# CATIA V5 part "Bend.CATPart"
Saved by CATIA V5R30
Part number: Bend
Bounding box of the stored display mesh (mm): x -50 to 50, y -150 to 15, z -50 to 115
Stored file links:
  D:\PROJECTS\CATIA V56R 2020\Resources\Parts File\c12_catia_v5_6r2020_prt\c12_catia_v5-6r2020figr_12-44\Bend.CATPart
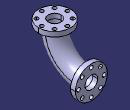
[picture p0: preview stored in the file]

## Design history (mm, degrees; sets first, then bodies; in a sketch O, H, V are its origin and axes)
Body1 (main body)
  Sketch1 on yz-plane, origin (0, 0, 0), H (0, 1, 0), V (0, 0, 1)
    arc A1 centre (0, 100) radius 100 from (-100, 100) to (0, 0) ccw
    point P1 (0, 100)
    coincidence: P1 V
  Sketch2 on zx-plane, origin (0, 0, 0), H (-1, 0, 0), V (0, 0, 1)
    circle A1 centre (0, 0) radius 30
    point P1 (0, -30)
    radius A1 = 30
    coincidence: A1 P1, P1 V
  Rib1: profile Sketch2, centre curve Sketch1
  Sketch3 on face of Rib1, origin (0, 0, 0), H (-1, 0, 0), V (0, 0, 1)
    circle A1 centre (0, 0) radius 50
    point P1 (0, -50)
    radius A1 = 50
    coincidence: A1 P1, P1 V
  Pad1: profile Sketch3, direction (0, 1, 0), length 15
  Sketch4 on face of Rib1, origin (0, 0, 100), H (1, 0, 0), V (0, 1, 0)
    circle A1 centre (0, -100) radius 50
    point P1 (0, -100)
    reference projected circle E1 centre (0, -100) radius 30 from edge [face of Rib1 | face of Rib1]
    radius A1 = 50
    coincidence: P1 V
    concentricity: A1 E1
  Pad2: profile Sketch4, direction (0, 0, 1), length 15
  Sketch5 on face of Pad1, origin (0, 15, 0), H (-1, 0, 0), V (0, 0, 1)
    circle A1 centre (0, 0) radius 20
    radius A1 = 20
  Sketch6 on yz-plane, origin (0, 0, 0), H (0, 1, 0), V (0, 0, 1)
    projected arc E1 centre (0, 100) radius 100 from (-100, 100) to (0, 0) ccw from edge of Sketch1
    line L1 (-100, 100) -> (-100, 115)
    point P3 (-100, 115)
    line L2 (0, 0) -> (15, 0)
    point P4 (15, 0)
    reference projected line E2 (15, 50) -> (15, -50) from edge [face of Pad1 | face of Pad1]
    reference projected line E3 (-50, 115) -> (-150, 115) from edge [face of Pad2 | face of Pad2]
    tangency: L1 E1, L2 E1
    coincidence: P4 E2, P3 E3
  Slot1: profile Sketch5, centre curve Sketch6
  Sketch7 on face of Pad1, origin (0, 15, 0), H (-1, 0, 0), V (0, 0, 1)
    circle A1 centre (0, -40) radius 6
    point P1 (0, -40)
    radius A1 = 6
    distance H P1 = 40
    coincidence: P1 V
  Pocket1: profile Sketch7, direction (0, -1, 0), length 15
  CircPattern1: of Pocket1, instances 8, angular step 45, axis from face of Pad1
  Sketch8 on face of Pad2, origin (0, 0, 115), H (1, 0, 0), V (0, 1, 0)
    circle A1 centre (0, -140) radius 6
    point P1 (0, -140)
    reference projected point E1 (0, -100) from vertex of Sketch1
    radius A1 = 6
    distance E1 P1 = 40
    coincidence: P1 V
  Pocket2: profile Sketch8, direction (0, 0, -1), length 15
  CircPattern2: of Pocket2, instances 8, angular step 45, axis from face of Pad2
